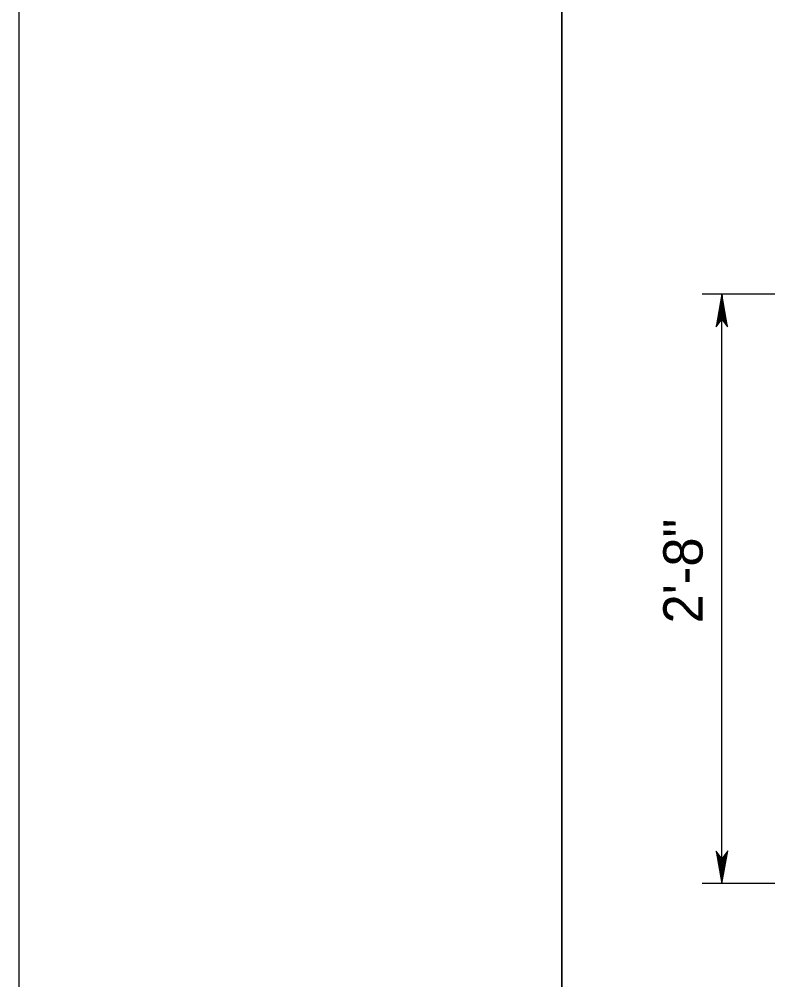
# Model space of a CAD drawing. Extents: x 499883 to 500983, y 499104 to 499764.
# Drawn here: x 499934.8 to 500012.1, y 499571.4 to 499669.1 of the extents above; entities that cross this region are included whole.
import ezdxf

# ---------------------------------------------------------------- set-up
doc = ezdxf.new("R2010")
doc.units = 0
for name, color, linetype in [('1', 7, 'Continuous'), ('41', 7, 'Continuous'), ('5', 7, 'Continuous')]:
    doc.layers.add(name, color=color, linetype=linetype)

msp = doc.modelspace()

# ---------------------------------------------------------------- linework, layer by layer
at = {"layer": '1'}
msp.add_line((499989.939, 499748.639), (499989.939, 499118.639), dxfattribs=at)
msp.add_line((499989.939, 499748.639), (499989.939, 499118.639), dxfattribs=at)
at = {"layer": '41'}
for points in [[(499934.766, 499763.639), (500982.939, 499763.639), (500982.939, 499103.639), (499934.766, 499103.639)], [(499989.939, 499748.639), (500979.939, 499748.639), (500979.939, 499118.639), (499989.939, 499118.639)]]:
    msp.add_lwpolyline(points, close=True, dxfattribs=at)
at = {"layer": '5'}
for p, q in [((500011.593, 499641.156), (500004.223, 499641.156)), ((500006.222, 499581.202), (500006.222, 499641.156)), ((500011.593, 499581.202), (500004.223, 499581.202))]:
    msp.add_line(p, q, dxfattribs=at)
for points in [[(500006.222, 499641.156), (500005.634, 499637.833), (500006.222, 499638.627), (500006.8, 499637.85), (500006.222, 499641.156), (500006.228, 499640.936), (500005.678, 499637.926), (500006.229, 499638.689), (500006.754, 499637.984), (500006.238, 499640.817), (500006.222, 499640.706), (500005.763, 499638.128), (500006.228, 499638.706), (500006.68, 499638.111), (500006.222, 499640.655), (500006.238, 499640.545), (500005.831, 499638.291), (500006.222, 499638.73), (500006.627, 499638.282), (500006.239, 499640.224), (500006.238, 499640.036), (500005.915, 499638.459), (500006.212, 499638.765), (500006.543, 499638.435), (500006.222, 499640.003), (500006.211, 499639.825), (500006.008, 499638.639), (500006.239, 499638.867), (500006.466, 499638.62), (500006.222, 499639.662), (500006.204, 499639.495), (500006.068, 499638.782), (500006.229, 499638.9), (500006.406, 499638.706), (500006.221, 499639.408), (500006.111, 499638.943), (500006.238, 499639.01), (500006.366, 499638.807), (500006.239, 499639.291), (500006.162, 499638.986), (500006.263, 499639.114), (500006.322, 499638.967), (500006.229, 499639.114), (500006.212, 499639.037)], [(500006.222, 499581.202), (500006.809, 499584.526), (500006.222, 499583.732), (500005.643, 499584.509), (500006.222, 499581.202), (500006.215, 499581.423), (500006.766, 499584.433), (500006.214, 499583.67), (500005.689, 499584.375), (500006.205, 499581.542), (500006.222, 499581.653), (500006.68, 499584.231), (500006.215, 499583.653), (500005.764, 499584.248), (500006.222, 499581.703), (500006.205, 499581.814), (500006.612, 499584.068), (500006.222, 499583.629), (500005.816, 499584.077), (500006.204, 499582.135), (500006.205, 499582.322), (500006.528, 499583.9), (500006.231, 499583.593), (500005.9, 499583.924), (500006.222, 499582.356), (500006.232, 499582.533), (500006.435, 499583.72), (500006.204, 499583.492), (500005.977, 499583.739), (500006.222, 499582.697), (500006.239, 499582.864), (500006.375, 499583.577), (500006.214, 499583.459), (500006.037, 499583.653), (500006.222, 499582.951), (500006.332, 499583.416), (500006.205, 499583.348), (500006.078, 499583.552), (500006.204, 499583.067), (500006.281, 499583.373), (500006.181, 499583.245), (500006.121, 499583.392), (500006.214, 499583.246), (500006.231, 499583.322)]]:
    msp.add_lwpolyline(points, dxfattribs=at)

# ---------------------------------------------------------------- texts
msp.add_text('2\'-8"', height=4, rotation=90, dxfattribs=at).set_placement((500004.256, 499607.658))

doc.saveas('drawing.dxf')
